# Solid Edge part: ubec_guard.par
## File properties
Author: wojci
Template: iso metric part.par
Last saved by: wojci
Revision: 1
Application: Solid Edge
Accuracy: 0.990
Username: wojci
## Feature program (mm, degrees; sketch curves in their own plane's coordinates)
sketch for "unnamed Protrusion 1" plane through (0, 0, 0) normal (0, 0, 1) x-axis (1, 0, 0)
  line (-7, -20) -> (3, -20)
  line (7, -16) -> (7, 20)
  line (7, 20) -> (-7, 20)
  line (-7, 20) -> (-7, -20)
extrude "unnamed Protrusion 1" add finite 3 along +normal
sketch for "ExtrudedProtrusion_3" plane through (2, -2, 3) normal (0, 0, 1) x-axis (1, 0, 0)
  circle centre (5, -18) radius 4
extrude "ExtrudedProtrusion_3" add finite 6.5 along +normal
sketch for "unnamed Cutout 1" #1 plane through (0, 0, 3) normal (0, 0, 1) x-axis (1, 0, 0)
  line (6, 20) -> (6, -10)
  line (6, -10) -> (7, -10)
  line (7, -10) -> (7, 20)
  line (7, 20) -> (6, 20)
sketch for "unnamed Cutout 1" #2 plane through (0, 0, 3) normal (0, 0, 1) x-axis (1, 0, 0)
  line (-4, 9) -> (-1, 9)
  line (-1, 9) -> (-1, -9)
  line (-1, -9) -> (-4, -9)
  line (-4, -9) -> (-4, 9)
extrude "unnamed Cutout 1" cut through along -normal
sketch for "ExtrudedCutout_2" plane through (0, 0, 3) normal (0, 0, 1) x-axis (1, 0, 0)
  line (1, -20) -> (1, 20)
  line (1, 20) -> (-2, 20)
  line (-2, 20) -> (-2, -20)
  line (-2, -20) -> (1, -20)
extrude "ExtrudedCutout_2" cut finite 1 along -normal
chamfer "Chamfer_1" setback 1
fillet "Round_1" radius 8
fillet "Round_2" radius 1.5
sketch for "Hole_1" plane through (2, -2, 0) normal (0, 0, -1) x-axis (-1, 0, 0)
  hole centre (-5, -18) bore radius 1.6
hole "Hole_1" diameter 3.2 through  CounterBoreDepth = 1.5 mm
sketch for "ExtrudedProtrusion_5" #1 plane through (-4.5, 0, 3) normal (0, 0, 1) x-axis (0, 1, 0)
  line (-20, 2.5) -> (20, 2.5)
  line (20, 2.5) -> (20, 1.5)
  line (20, 1.5) -> (-20, 1.5)
  line (-20, 1.5) -> (-20, 2.5)
  dimension (linear) = 20
  dimension (linear) = 20
sketch for "ExtrudedProtrusion_5" #2 plane through (-4.5, 0, 3) normal (0, 0, 1) x-axis (0, 1, 0)
  line (-20, -7.5) -> (20, -7.5)
  line (20, -7.5) -> (20, -9.5)
  line (20, -9.5) -> (-20, -9.5)
  line (-20, -9.5) -> (-20, -7.5)
extrude "ExtrudedProtrusion_5" add finite 1 along +normal
sketch for "ExtrudedProtrusion_6" plane through (7.3333, 1.4907, 3) normal (0, 0, 1) x-axis (0, -1, 0)
  arc centre (12.5464, 7.6667) radius 8 from (18.5093, 2.3333) to (12.5464, -0.3333) cw
  line (12.5464, -0.3333) -> (10.5464, -2.3333)
  line (10.5464, -2.3333) -> (18.0266, -2.3333)
  line (18.0266, -2.3333) -> (18.5093, 2.3333)
extrude "ExtrudedProtrusion_6" add finite 1 along +normal
chamfer "Chamfer_2" setback 1
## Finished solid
Body 1: solid body, 31 faces, 82 edges, 51 vertices.
  Faces by surface: plane 24, cylinder 7
  Edges by curve: line 61, circle 19, ellipse 2
Bounding box of the edges (mm): 18.000 x 44.000 x 9.500, from (-7, -24, 0) to (11, 20, 9.5).
Cylindrical faces by radius (mm): R1.5 x2, R1.6 x1, R3.25 x1, R4 x1, R8 x2
Planar faces by outward normal: +x 5, +y 1, +z 7, -x 4, -y 1, -z 2, oblique 4
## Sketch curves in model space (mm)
line (1, 20, 3) -> (1, -20, 3)
line (6, 20, 3) -> (6, -10, 3)
line (6, -10, 3) -> (7, -10, 3)
line (7, -10, 3) -> (7, 20, 3)
line (7, 20, 3) -> (6, 20, 3)
line (-1, 9, 3) -> (-1, -9, 3)
line (-1, -9, 3) -> (-4, -9, 3)
line (-4, -9, 3) -> (-4, 9, 3)
line (-4, 9, 3) -> (-1, 9, 3)
line (-2, 20, 3) -> (-2, -20, 3)
line (-2, -20, 3) -> (1, -20, 3)
line (1, -20, 3) -> (1, 20, 3)
line (1, 20, 3) -> (-2, 20, 3)
arc centre (7, -20, 0) radius 4 from (7, -16, 0) through (9.7428, -22.9115, 0) to (3, -20, 0)
line (7, -16, 0) -> (7, 20, 0)
line (7, 20, 0) -> (-7, 20, 0)
line (-7, 20, 0) -> (-7, -20, 0)
line (-7, -20, 0) -> (3, -20, 0)
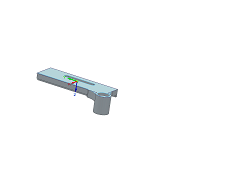
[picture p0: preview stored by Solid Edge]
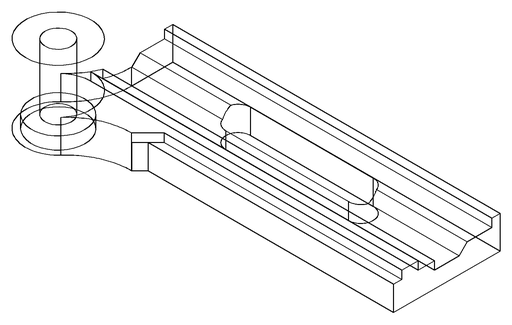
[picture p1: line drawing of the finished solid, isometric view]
